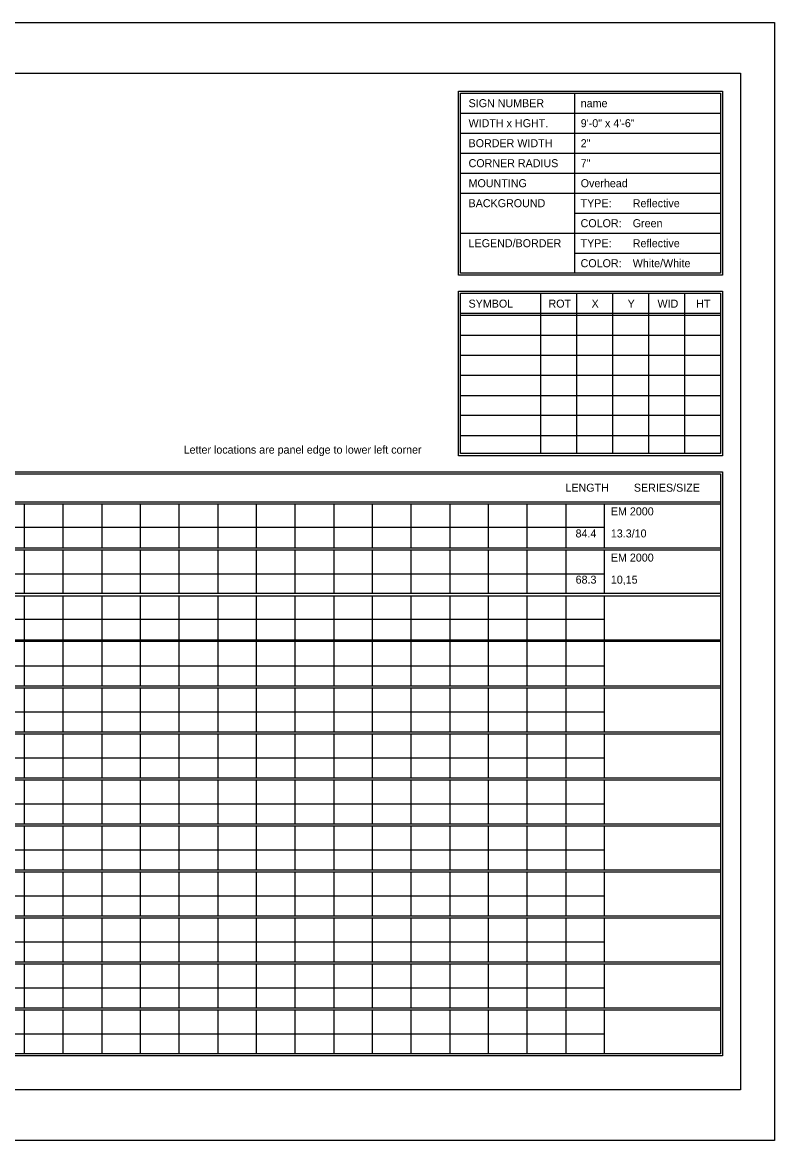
# Model space of a CAD drawing. Extents: x 1806251 to 1809821, y 414895 to 422886.
# Drawn here: x 1809679.34 to 1809684.89, y 414894.66 to 414902.91 of the extents above; entities that cross this region are included whole.
import ezdxf

# ---------------------------------------------------------------- set-up
doc = ezdxf.new("R2010")
doc.units = 0
doc.layers.add('GSSHT', color=7, linetype='Continuous')

msp = doc.modelspace()

# ---------------------------------------------------------------- linework, layer by layer
at = {"layer": 'GSSHT'}
for p, q in [((1809672.1343, 414902.9092), (1809684.8885, 414902.9092)), ((1809684.8885, 414902.9092), (1809684.8885, 414894.6554)), ((1809683.412, 414902.3865), (1809683.412, 414901.0576)), ((1809682.5704, 414902.2388), (1809684.4899, 414902.2388)), ((1809682.5704, 414902.0912), (1809684.4899, 414902.0912)), ((1809682.5704, 414901.9435), (1809684.4899, 414901.9435)), ((1809682.5704, 414901.7959), (1809684.4899, 414901.7959)), ((1809682.5704, 414901.6482), (1809684.4899, 414901.6482)), ((1809683.412, 414901.5006), (1809684.4899, 414901.5006)), ((1809682.5704, 414901.3529), (1809684.4899, 414901.3529)), ((1809683.412, 414901.2052), (1809684.4899, 414901.2052)), ((1809683.161, 414900.9099), (1809683.161, 414899.7258)), ((1809683.4268, 414900.9099), (1809683.4268, 414899.7258)), ((1809683.6926, 414900.9099), (1809683.6926, 414899.7258)), ((1809683.9583, 414900.9099), (1809683.9583, 414899.7258)), ((1809684.2241, 414900.9099), (1809684.2241, 414899.7258)), ((1809682.5704, 414900.7623), (1809684.4899, 414900.7623)), ((1809682.5704, 414900.7475), (1809684.4899, 414900.7475)), ((1809682.5704, 414900.5999), (1809684.4899, 414900.5999)), ((1809682.5704, 414900.4522), (1809684.4899, 414900.4522)), ((1809682.5704, 414900.3046), (1809684.4899, 414900.3046)), ((1809682.5704, 414900.154), (1809684.4899, 414900.154)), ((1809682.5704, 414900.0093), (1809684.4899, 414900.0093)), ((1809682.5704, 414899.8587), (1809684.4899, 414899.8587)), ((1809672.781, 414899.3714), (1809684.4899, 414899.3714)), ((1809672.781, 414899.3566), (1809684.4899, 414899.3566)), ((1809679.3486, 414899.3566), (1809679.3486, 414899.0318)), ((1809679.6351, 414899.3566), (1809679.6351, 414899.0318)), ((1809679.9215, 414899.3566), (1809679.9215, 414899.0318)), ((1809680.205, 414899.3566), (1809680.205, 414899.0318)), ((1809680.4914, 414899.3566), (1809680.4914, 414899.0318)), ((1809680.7779, 414899.3566), (1809680.7779, 414899.0318)), ((1809681.0614, 414899.3566), (1809681.0614, 414899.0318)), ((1809681.3478, 414899.3566), (1809681.3478, 414899.0318)), ((1809681.6343, 414899.3566), (1809681.6343, 414899.0318)), ((1809681.9178, 414899.3566), (1809681.9178, 414899.0318)), ((1809682.2042, 414899.3566), (1809682.2042, 414899.0318)), ((1809682.4907, 414899.3566), (1809682.4907, 414899.0318)), ((1809682.7742, 414899.3566), (1809682.7742, 414899.0318)), ((1809683.0606, 414899.3566), (1809683.0606, 414899.0318)), ((1809683.347, 414899.3566), (1809683.347, 414899.0318)), ((1809683.6305, 414899.3566), (1809683.6305, 414899.0318)), ((1809672.781, 414899.1824), (1809683.6305, 414899.1824)), ((1809672.781, 414899.0318), (1809684.4899, 414899.0318)), ((1809672.781, 414899.017), (1809684.4899, 414899.017)), ((1809679.3486, 414899.017), (1809679.3486, 414898.6952)), ((1809679.6351, 414899.017), (1809679.6351, 414898.6952)), ((1809679.9215, 414899.017), (1809679.9215, 414898.6952)), ((1809680.205, 414899.017), (1809680.205, 414898.6952)), ((1809680.4914, 414899.017), (1809680.4914, 414898.6952)), ((1809680.7779, 414899.017), (1809680.7779, 414898.6952)), ((1809681.0614, 414899.017), (1809681.0614, 414898.6952)), ((1809681.3478, 414899.017), (1809681.3478, 414898.6952)), ((1809681.6343, 414899.017), (1809681.6343, 414898.6952)), ((1809681.9178, 414899.017), (1809681.9178, 414898.6952)), ((1809682.2042, 414899.017), (1809682.2042, 414898.6952)), ((1809682.4907, 414899.017), (1809682.4907, 414898.6952)), ((1809682.7742, 414899.017), (1809682.7742, 414898.6952)), ((1809683.0606, 414899.017), (1809683.0606, 414898.6952)), ((1809683.347, 414899.017), (1809683.347, 414898.6952)), ((1809683.6305, 414899.017), (1809683.6305, 414898.6952)), ((1809672.781, 414898.8399), (1809683.6305, 414898.8399)), ((1809672.781, 414898.6952), (1809684.4899, 414898.6952)), ((1809672.781, 414898.6774), (1809684.4899, 414898.6774)), ((1809679.3486, 414898.6774), (1809679.3486, 414898.3526)), ((1809679.6351, 414898.6774), (1809679.6351, 414898.3526)), ((1809679.9215, 414898.6774), (1809679.9215, 414898.3526)), ((1809680.205, 414898.6774), (1809680.205, 414898.3526)), ((1809680.4914, 414898.6774), (1809680.4914, 414898.3526)), ((1809680.7779, 414898.6774), (1809680.7779, 414898.3526)), ((1809681.0614, 414898.6774), (1809681.0614, 414898.3526)), ((1809681.3478, 414898.6774), (1809681.3478, 414898.3526)), ((1809681.6343, 414898.6774), (1809681.6343, 414898.3526)), ((1809681.9178, 414898.6774), (1809681.9178, 414898.3526)), ((1809682.2042, 414898.6774), (1809682.2042, 414898.3526)), ((1809682.4907, 414898.6774), (1809682.4907, 414898.3526)), ((1809682.7742, 414898.6774), (1809682.7742, 414898.3526)), ((1809683.0606, 414898.6774), (1809683.0606, 414898.3526)), ((1809683.347, 414898.6774), (1809683.347, 414898.3526)), ((1809683.6305, 414898.6774), (1809683.6305, 414898.3526)), ((1809672.781, 414898.5032), (1809683.6305, 414898.5032)), ((1809672.781, 414898.3526), (1809684.4899, 414898.3526)), ((1809672.781, 414898.3408), (1809684.4899, 414898.3408)), ((1809679.3486, 414898.3408), (1809679.3486, 414898.013)), ((1809679.6351, 414898.3408), (1809679.6351, 414898.013)), ((1809679.9215, 414898.3408), (1809679.9215, 414898.013)), ((1809680.205, 414898.3408), (1809680.205, 414898.013)), ((1809680.4914, 414898.3408), (1809680.4914, 414898.013)), ((1809680.7779, 414898.3408), (1809680.7779, 414898.013)), ((1809681.0614, 414898.3408), (1809681.0614, 414898.013)), ((1809681.3478, 414898.3408), (1809681.3478, 414898.013)), ((1809681.6343, 414898.3408), (1809681.6343, 414898.013)), ((1809681.9178, 414898.3408), (1809681.9178, 414898.013)), ((1809682.2042, 414898.3408), (1809682.2042, 414898.013)), ((1809682.4907, 414898.3408), (1809682.4907, 414898.013)), ((1809682.7742, 414898.3408), (1809682.7742, 414898.013)), ((1809683.0606, 414898.3408), (1809683.0606, 414898.013)), ((1809683.347, 414898.3408), (1809683.347, 414898.013)), ((1809683.6305, 414898.3408), (1809683.6305, 414898.013)), ((1809672.781, 414898.1607), (1809683.6305, 414898.1607)), ((1809672.781, 414898.013), (1809684.4899, 414898.013)), ((1809672.781, 414897.9982), (1809684.4899, 414897.9982)), ((1809679.3486, 414897.9982), (1809679.3486, 414897.6734)), ((1809679.6351, 414897.9982), (1809679.6351, 414897.6734)), ((1809679.9215, 414897.9982), (1809679.9215, 414897.6734)), ((1809680.205, 414897.9982), (1809680.205, 414897.6734)), ((1809680.4914, 414897.9982), (1809680.4914, 414897.6734)), ((1809680.7779, 414897.9982), (1809680.7779, 414897.6734)), ((1809681.0614, 414897.9982), (1809681.0614, 414897.6734)), ((1809681.3478, 414897.9982), (1809681.3478, 414897.6734)), ((1809681.6343, 414897.9982), (1809681.6343, 414897.6734)), ((1809681.9178, 414897.9982), (1809681.9178, 414897.6734)), ((1809682.2042, 414897.9982), (1809682.2042, 414897.6734)), ((1809682.4907, 414897.9982), (1809682.4907, 414897.6734)), ((1809682.7742, 414897.9982), (1809682.7742, 414897.6734)), ((1809683.0606, 414897.9982), (1809683.0606, 414897.6734)), ((1809683.347, 414897.9982), (1809683.347, 414897.6734)), ((1809683.6305, 414897.9982), (1809683.6305, 414897.6734)), ((1809672.781, 414897.821), (1809683.6305, 414897.821)), ((1809672.781, 414897.6734), (1809684.4899, 414897.6734)), ((1809672.781, 414897.6586), (1809684.4899, 414897.6586)), ((1809679.3486, 414897.6586), (1809679.3486, 414897.3338)), ((1809679.6351, 414897.6586), (1809679.6351, 414897.3338)), ((1809679.9215, 414897.6586), (1809679.9215, 414897.3338)), ((1809680.205, 414897.6586), (1809680.205, 414897.3338)), ((1809680.4914, 414897.6586), (1809680.4914, 414897.3338)), ((1809680.7779, 414897.6586), (1809680.7779, 414897.3338)), ((1809681.0614, 414897.6586), (1809681.0614, 414897.3338)), ((1809681.3478, 414897.6586), (1809681.3478, 414897.3338)), ((1809681.6343, 414897.6586), (1809681.6343, 414897.3338)), ((1809681.9178, 414897.6586), (1809681.9178, 414897.3338)), ((1809682.2042, 414897.6586), (1809682.2042, 414897.3338)), ((1809682.4907, 414897.6586), (1809682.4907, 414897.3338)), ((1809682.7742, 414897.6586), (1809682.7742, 414897.3338)), ((1809683.0606, 414897.6586), (1809683.0606, 414897.3338)), ((1809683.347, 414897.6586), (1809683.347, 414897.3338)), ((1809683.6305, 414897.6586), (1809683.6305, 414897.3338)), ((1809672.781, 414897.4814), (1809683.6305, 414897.4814)), ((1809672.781, 414897.3338), (1809684.4899, 414897.3338)), ((1809672.781, 414897.319), (1809684.4899, 414897.319)), ((1809679.3486, 414897.319), (1809679.3486, 414896.9942)), ((1809679.6351, 414897.319), (1809679.6351, 414896.9942)), ((1809679.9215, 414897.319), (1809679.9215, 414896.9942)), ((1809680.205, 414897.319), (1809680.205, 414896.9942)), ((1809680.4914, 414897.319), (1809680.4914, 414896.9942)), ((1809680.7779, 414897.319), (1809680.7779, 414896.9942)), ((1809681.0614, 414897.319), (1809681.0614, 414896.9942)), ((1809681.3478, 414897.319), (1809681.3478, 414896.9942)), ((1809681.6343, 414897.319), (1809681.6343, 414896.9942)), ((1809681.9178, 414897.319), (1809681.9178, 414896.9942)), ((1809682.2042, 414897.319), (1809682.2042, 414896.9942)), ((1809682.4907, 414897.319), (1809682.4907, 414896.9942)), ((1809682.7742, 414897.319), (1809682.7742, 414896.9942)), ((1809683.0606, 414897.319), (1809683.0606, 414896.9942)), ((1809683.347, 414897.319), (1809683.347, 414896.9942)), ((1809683.6305, 414897.319), (1809683.6305, 414896.9942)), ((1809672.781, 414897.1418), (1809683.6305, 414897.1418)), ((1809672.781, 414896.9942), (1809684.4899, 414896.9942)), ((1809672.781, 414896.9794), (1809684.4899, 414896.9794)), ((1809679.3486, 414896.9794), (1809679.3486, 414896.6546)), ((1809679.6351, 414896.9794), (1809679.6351, 414896.6546)), ((1809679.9215, 414896.9794), (1809679.9215, 414896.6546)), ((1809680.205, 414896.9794), (1809680.205, 414896.6546)), ((1809680.4914, 414896.9794), (1809680.4914, 414896.6546)), ((1809680.7779, 414896.9794), (1809680.7779, 414896.6546)), ((1809681.0614, 414896.9794), (1809681.0614, 414896.6546)), ((1809681.3478, 414896.9794), (1809681.3478, 414896.6546)), ((1809681.6343, 414896.9794), (1809681.6343, 414896.6546)), ((1809681.9178, 414896.9794), (1809681.9178, 414896.6546)), ((1809682.2042, 414896.9794), (1809682.2042, 414896.6546)), ((1809682.4907, 414896.9794), (1809682.4907, 414896.6546)), ((1809682.7742, 414896.9794), (1809682.7742, 414896.6546)), ((1809683.0606, 414896.9794), (1809683.0606, 414896.6546)), ((1809683.347, 414896.9794), (1809683.347, 414896.6546)), ((1809683.6305, 414896.9794), (1809683.6305, 414896.6546)), ((1809672.781, 414896.8022), (1809683.6305, 414896.8022)), ((1809672.781, 414896.6546), (1809684.4899, 414896.6546)), ((1809672.781, 414896.6398), (1809684.4899, 414896.6398)), ((1809679.3486, 414896.6398), (1809679.3486, 414896.315)), ((1809679.6351, 414896.6398), (1809679.6351, 414896.315)), ((1809679.9215, 414896.6398), (1809679.9215, 414896.315)), ((1809680.205, 414896.6398), (1809680.205, 414896.315)), ((1809680.4914, 414896.6398), (1809680.4914, 414896.315)), ((1809680.7779, 414896.6398), (1809680.7779, 414896.315)), ((1809681.0614, 414896.6398), (1809681.0614, 414896.315)), ((1809681.3478, 414896.6398), (1809681.3478, 414896.315)), ((1809681.6343, 414896.6398), (1809681.6343, 414896.315)), ((1809681.9178, 414896.6398), (1809681.9178, 414896.315)), ((1809682.2042, 414896.6398), (1809682.2042, 414896.315)), ((1809682.4907, 414896.6398), (1809682.4907, 414896.315)), ((1809682.7742, 414896.6398), (1809682.7742, 414896.315)), ((1809683.0606, 414896.6398), (1809683.0606, 414896.315)), ((1809683.347, 414896.6398), (1809683.347, 414896.315)), ((1809683.6305, 414896.6398), (1809683.6305, 414896.315)), ((1809672.781, 414896.4626), (1809683.6305, 414896.4626)), ((1809672.781, 414896.315), (1809684.4899, 414896.315)), ((1809672.781, 414896.3002), (1809684.4899, 414896.3002)), ((1809679.3486, 414896.3002), (1809679.3486, 414895.9754)), ((1809679.6351, 414896.3002), (1809679.6351, 414895.9754)), ((1809679.9215, 414896.3002), (1809679.9215, 414895.9754)), ((1809680.205, 414896.3002), (1809680.205, 414895.9754)), ((1809680.4914, 414896.3002), (1809680.4914, 414895.9754)), ((1809680.7779, 414896.3002), (1809680.7779, 414895.9754)), ((1809681.0614, 414896.3002), (1809681.0614, 414895.9754)), ((1809681.3478, 414896.3002), (1809681.3478, 414895.9754)), ((1809681.6343, 414896.3002), (1809681.6343, 414895.9754)), ((1809681.9178, 414896.3002), (1809681.9178, 414895.9754)), ((1809682.2042, 414896.3002), (1809682.2042, 414895.9754)), ((1809682.4907, 414896.3002), (1809682.4907, 414895.9754)), ((1809682.7742, 414896.3002), (1809682.7742, 414895.9754)), ((1809683.0606, 414896.3002), (1809683.0606, 414895.9754)), ((1809683.347, 414896.3002), (1809683.347, 414895.9754)), ((1809683.6305, 414896.3002), (1809683.6305, 414895.9754)), ((1809672.781, 414896.123), (1809683.6305, 414896.123)), ((1809672.781, 414895.9754), (1809684.4899, 414895.9754)), ((1809672.781, 414895.9606), (1809684.4899, 414895.9606)), ((1809679.3486, 414895.9606), (1809679.3486, 414895.6358)), ((1809679.6351, 414895.9606), (1809679.6351, 414895.6358)), ((1809679.9215, 414895.9606), (1809679.9215, 414895.6358)), ((1809680.205, 414895.9606), (1809680.205, 414895.6358)), ((1809680.4914, 414895.9606), (1809680.4914, 414895.6358)), ((1809680.7779, 414895.9606), (1809680.7779, 414895.6358)), ((1809681.0614, 414895.9606), (1809681.0614, 414895.6358)), ((1809681.3478, 414895.9606), (1809681.3478, 414895.6358)), ((1809681.6343, 414895.9606), (1809681.6343, 414895.6358)), ((1809681.9178, 414895.9606), (1809681.9178, 414895.6358)), ((1809682.2042, 414895.9606), (1809682.2042, 414895.6358)), ((1809682.4907, 414895.9606), (1809682.4907, 414895.6358)), ((1809682.7742, 414895.9606), (1809682.7742, 414895.6358)), ((1809683.0606, 414895.9606), (1809683.0606, 414895.6358)), ((1809683.347, 414895.9606), (1809683.347, 414895.6358)), ((1809683.6305, 414895.9606), (1809683.6305, 414895.6358)), ((1809672.781, 414895.7834), (1809683.6305, 414895.7834)), ((1809672.781, 414895.6358), (1809684.4899, 414895.6358)), ((1809672.781, 414895.621), (1809684.4899, 414895.621)), ((1809679.3486, 414895.621), (1809679.3486, 414895.2962)), ((1809679.6351, 414895.621), (1809679.6351, 414895.2962)), ((1809679.9215, 414895.621), (1809679.9215, 414895.2962)), ((1809680.205, 414895.621), (1809680.205, 414895.2962)), ((1809680.4914, 414895.621), (1809680.4914, 414895.2962)), ((1809680.7779, 414895.621), (1809680.7779, 414895.2962)), ((1809681.0614, 414895.621), (1809681.0614, 414895.2962)), ((1809681.3478, 414895.621), (1809681.3478, 414895.2962)), ((1809681.6343, 414895.621), (1809681.6343, 414895.2962)), ((1809681.9178, 414895.621), (1809681.9178, 414895.2962)), ((1809682.2042, 414895.621), (1809682.2042, 414895.2962)), ((1809682.4907, 414895.621), (1809682.4907, 414895.2962)), ((1809682.7742, 414895.621), (1809682.7742, 414895.2962)), ((1809683.0606, 414895.621), (1809683.0606, 414895.2962)), ((1809683.347, 414895.621), (1809683.347, 414895.2962)), ((1809683.6305, 414895.621), (1809683.6305, 414895.2962)), ((1809672.781, 414895.4438), (1809683.6305, 414895.4438)), ((1809684.8885, 414894.6554), (1809672.1343, 414894.6554))]:
    msp.add_line(p, q, dxfattribs=at)
for points in [[(1809672.6334, 414902.5341), (1809684.6375, 414902.5341), (1809684.6375, 414895.0304), (1809672.6334, 414895.0304)], [(1809682.5556, 414902.4012), (1809684.5046, 414902.4012), (1809684.5046, 414901.0428), (1809682.5556, 414901.0428)], [(1809682.5704, 414902.3865), (1809684.4899, 414902.3865), (1809684.4899, 414901.0576), (1809682.5704, 414901.0576)], [(1809682.5556, 414900.9247), (1809684.5046, 414900.9247), (1809684.5046, 414899.711), (1809682.5556, 414899.711)], [(1809682.5704, 414900.9099), (1809684.4899, 414900.9099), (1809684.4899, 414899.7258), (1809682.5704, 414899.7258)], [(1809672.7663, 414899.5929), (1809684.5046, 414899.5929), (1809684.5046, 414895.2814), (1809672.7663, 414895.2814)], [(1809672.781, 414899.5781), (1809684.4899, 414899.5781), (1809684.4899, 414895.2962), (1809672.781, 414895.2962)]]:
    msp.add_lwpolyline(points, close=True, dxfattribs=at)

# ---------------------------------------------------------------- texts
for s, height, p in [('SIGN NUMBER', 0.059055, (1809682.6295, 414902.2831)), ('name', 0.05906, (1809683.4573, 414902.283)), ('WIDTH x HGHT.', 0.059055, (1809682.6295, 414902.1355)), ('9\'-0" x 4\'-6"', 0.059055, (1809683.4573, 414902.1354)), ('BORDER WIDTH', 0.059055, (1809682.6295, 414901.9878)), ('2"', 0.05906, (1809683.4573, 414901.9877)), ('CORNER RADIUS', 0.059055, (1809682.6295, 414901.8402)), ('7"', 0.05906, (1809683.4573, 414901.8401)), ('MOUNTING', 0.05906, (1809682.6295, 414901.6925)), ('Overhead', 0.05906, (1809683.4573, 414901.6924)), ('BACKGROUND', 0.05906, (1809682.6295, 414901.5448)), ('TYPE:', 0.05906, (1809683.4563, 414901.5448)), ('Reflective', 0.05906, (1809683.8412, 414901.5448)), ('COLOR:', 0.05906, (1809683.4563, 414901.3972)), ('Green', 0.05906, (1809683.8412, 414901.3972)), ('LEGEND/BORDER', 0.059055, (1809682.6295, 414901.2495)), ('TYPE:', 0.05906, (1809683.4563, 414901.2495)), ('Reflective', 0.05906, (1809683.8412, 414901.2495)), ('COLOR:', 0.05906, (1809683.4563, 414901.1019)), ('White/White', 0.059055, (1809683.8412, 414901.1019)), ('SYMBOL', 0.05906, (1809682.6295, 414900.8036)), ('ROT', 0.05906, (1809683.2194, 414900.8036)), ('X', 0.0591, (1809683.5374, 414900.8036)), ('Y', 0.0591, (1809683.8035, 414900.8036)), ('WID', 0.05906, (1809684.024, 414900.8036)), ('HT', 0.05906, (1809684.3096, 414900.8036)), ('Letter locations are panel edge to lower left corner', 0.059055, (1809680.5266, 414899.7259)), ('LENGTH', 0.05906, (1809683.3444, 414899.4452)), ('SERIES/SIZE', 0.059061, (1809683.8496, 414899.4452)), ('EM 2000', 0.05906, (1809683.6797, 414899.2703)), ('84.4', 0.05906, (1809683.4192, 414899.1075)), ('13.3/10', 0.05906, (1809683.6797, 414899.1075)), ('EM 2000', 0.05906, (1809683.6797, 414898.9292)), ('68.3', 0.05906, (1809683.4196, 414898.7664)), ('10,15', 0.05906, (1809683.6797, 414898.7664))]:
    msp.add_text(s, height=height, dxfattribs=at).set_placement(p)

doc.saveas('drawing.dxf')
